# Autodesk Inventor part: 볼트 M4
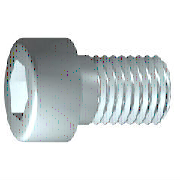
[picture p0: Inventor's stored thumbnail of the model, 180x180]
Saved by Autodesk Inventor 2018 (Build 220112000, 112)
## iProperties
Created: 2012-02
Part Number: 볼트 M4
Material: 스테인리스강
Description: 6각 소켓 머리 캡 나사
Document SubType Name: Modeling
Standard: ISO 4762
Designer: mduedu
Standard Revision: Fourth edition 2004-03-01
Standards Organization: ISO
Language: ko-KR
Size Designation: M4 x 16
Categories: <MemberInstance><Categories><Category DisplayName="조임쇠" InternalName="e4da775c-781d-43d5-af7c-5136215cf5a6" Mnemonic="FSTN"><Category DisplayName="볼트" InternalN
Density: 7.75 g/cm^3
Appearance: 반광택
IsCustomPart: 0
Author: mduedu
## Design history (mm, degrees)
sketch "스케치1"
  geometry: L1 (-1, 0)-(16, 0); L2 (16, 0)-(16, 2); L3 (16, 2)-(1.75, 2); L4 (1.75, 2)-(1.32, 2); L5 (1.32, 2)-(0, 2); L6 (0, 2)-(0, 3.5); L7 (0, 3.5)-(-4, 3.5); L8 (-4, 3.5)-(-4, 1.732); L9 (-4, 1.732)-(-2, 1.732); L10 (-2, 1.732)-(-1, 0); L11 (-8, 0)-(20, 0) reference; L12 (0, -0.7)-(0, 4.2) reference; L13 (1.75, 2)-(0, 2)
  constraints: 22 end point, 6 parallel, 2 collinear, 2 perpendicular, 1 horizontal, 1 point on line
  dimensions: "d1" = 14.25 distance from line of L3.end L2 (= GEL); "d2" = 0.42952 distance of L4.end L3.end (computed from GAL); "d3" = 4 distance between parallel lines of L8 L6 (= KOH); "d4" = 2 distance of L8.end L9.end (= INTI); "d5" = 60 deg angle of L10 L1; "d6" = 4 diameter of L3 L1 (= GD); "d7" = 4 diameter of L5 L1 (= BDM); "d8" = 3.4641 diameter of L9 L1 (= 1.1547 x SW); "d9" = 7 diameter of L7 L1 (= KOD); "d26" = 16 distance between parallel lines of L12 L2 (= NLG)
revolve "본체" sketch "스케치1" stored, may be unused: angle "d10" = 90 deg
sketch "스케치2"
  geometry: L1 (0, -4.9)-(0, 4.9) reference; L2 (-4.9, 0)-(4.9, 0) reference; L3 (1.732, 0)-(0.866, -1.5); L4 (0.866, -1.5)-(-0.866, -1.5); L5 (-0.866, -1.5)-(-1.732, 0); L6 (-1.732, 0)-(-0.866, 1.5); L7 (-0.866, 1.5)-(0.866, 1.5); L8 (0.866, 1.5)-(1.732, 0); 2 further points
  constraints: 12 end point, 1 coincident, 1 horizontal alignment, 1 point on line, 12 other
extrude "슬롯" join sketch "스케치2" stored distance "d11" = 10; taper "d12" = 0 deg
workplane "Work Plane1"
fillet "Fillet2" dims "d30" = 0.1 (= R)
body "Solid1"
fillet "모깎기1" dims "d17" = 0.4 (= RR)
feature "스레드" dims "d13" = 14.25 (= GEL), "d14" = 0
chamfer "모따기1" distance "d15" = 0.42941 (= -0.5 x SPD + 0.5 x GD); stored, may be unused: second distance "d16" = 0.42941 (= GUL), angle "d27" = 45 deg
other parameters: "GD" = 4 [user parameter; used in 2 equation terms], "NLG" = 16 [user parameter; used in 1 equation term], "GEL" = 14.25 [user parameter; used in 2 equation terms], "KOD" = 7 [user parameter; used in 1 equation term], "KOH" = 4 [user parameter; used in 1 equation term], "INTI" = 2 [user parameter; used in 1 equation term], "GAL" = 0.42941 (= 0.61345 x PTC) [user parameter; used in 1 equation term], "GUL" = 0.42941 (= 0.61345 x PTC) [user parameter; used in 1 equation term], "BDM" = 4 (= NND) [user parameter; used in 1 equation term], "SW" = 3 [user parameter; used in 2 equation terms], "RR" = 0.4 [user parameter; used in 1 equation term], "SPD" = 3.14117 (= NND - 1.2269 x PTC) [user parameter; used in 1 equation term], "d19" = 0, "d28" = 0, "d29" = 0, "R" = 0.1 [user parameter; used in 1 equation term], "TOA" = 30 deg [user parameter], "GD1" = 3.14117 (= THREADDIA - 1.2269 x PTC) [user parameter], "THREADDIA" = 4 [user parameter; used in 1 equation term], "FAWI" = 45 deg [user parameter], "TPU" = 14.28571 (computed from PTC) [user parameter], "PTC" = 0.7 [user parameter; used in 5 equation terms], "NND" = 4 [user parameter; used in 2 equation terms], "E0" = 3.465 (= 1.155 x SW) [user parameter]
